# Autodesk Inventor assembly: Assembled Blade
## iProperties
Shininess: 64.0
Length Units: 11272
Angle Units: 11279
Time Units: 11290
Mass Units: 11286
Length Display Precision: 3
Angle Display Precision: 2
Compacted: True
Part Number: Assembled Blade
Document SubType Name: Assembly
Created: 2003-10
Designer: jpittman
Manufacturer: Standard
Standards Organization: Custom
Density: 0.0
Volumn: 0.0
Area: 0.0
PropertySet Name: Model Information
Control State: 0
Master: False
Checked Out: False
Author: jpittman
